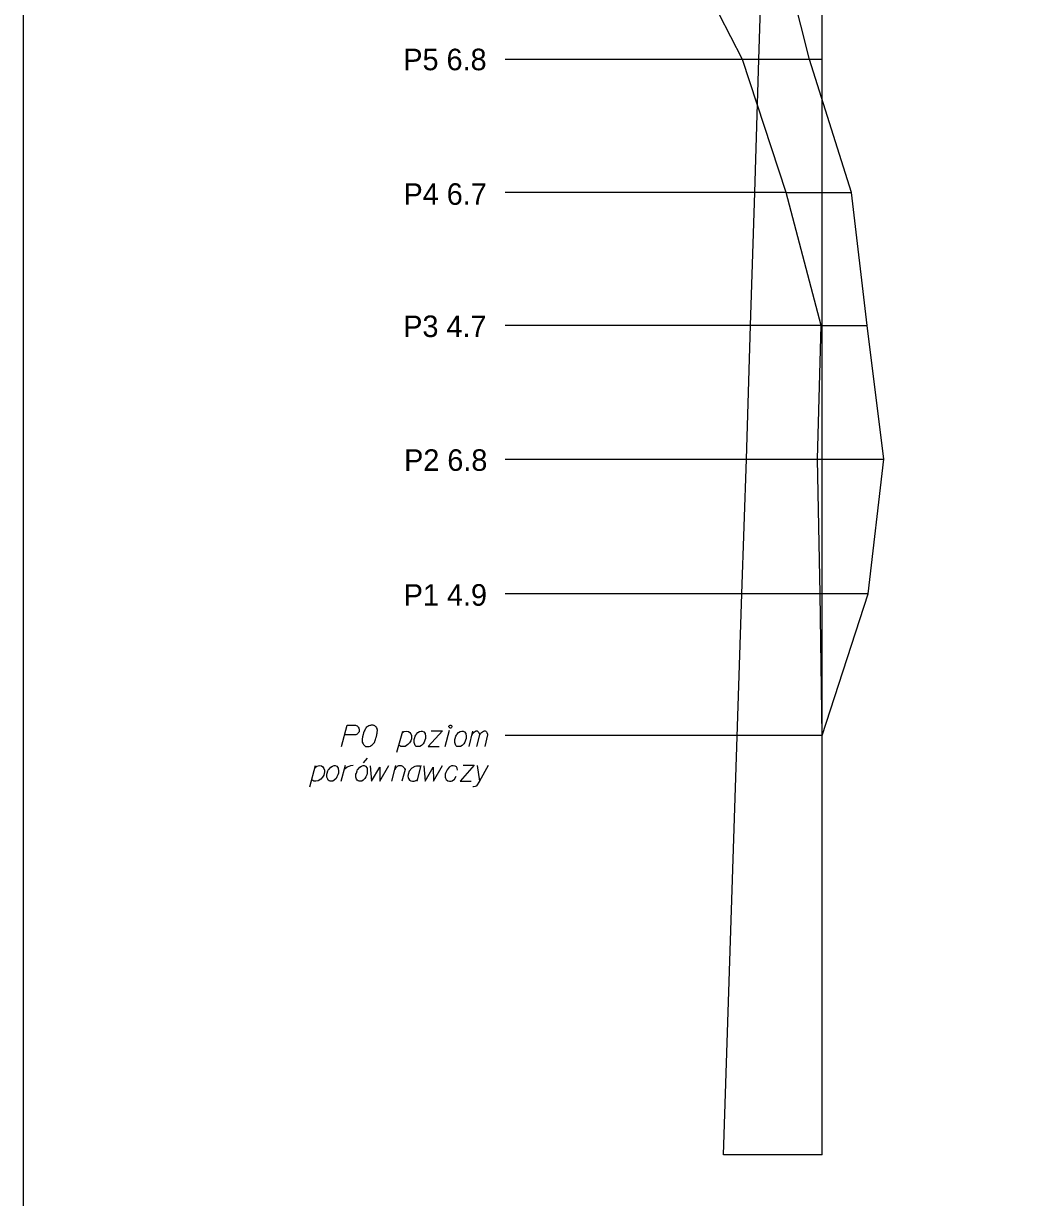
# Model space of a CAD drawing. Extents: x 138 to 264, y -75 to 121.
# Drawn here: x 227.52 to 237.85, y -57.33 to -45.34 of the extents above; entities that cross this region are included whole.
import ezdxf

# ---------------------------------------------------------------- set-up
doc = ezdxf.new("R2010")
doc.units = 0
for name, color, linetype in [('15 listopad 2008', 7, 'Continuous'), ('Ramka do drukowania', 7, 'Continuous'), ('Standart wykresów', 7, 'Continuous'), ('Wykresy 4 maj 2008', 7, 'Continuous')]:
    doc.layers.add(name, color=color, linetype=linetype)

msp = doc.modelspace()

# ---------------------------------------------------------------- linework, layer by layer
at = {"layer": '15 listopad 2008'}
msp.add_lwpolyline([(235.685, -52.61), (236.155, -51.164), (236.315, -49.788), (236.145, -48.421), (235.985, -47.063), (235.555, -45.704), (235.205, -44.313), (234.025, -42.911), (233.715, -41.918), (233.685, -40.937), (233.845, -40.478), (234.355, -39.961), (234.525, -39.493), (235.345, -38.925), (236.535, -38.4), (236.595, -38.212), (240.695, -37.514), (243.055, -37.151), (244.125, -36.895)], dxfattribs=at)
at = {"layer": 'Ramka do drukowania'}
msp.add_line((227.525, -63.621), (227.525, -33.921), dxfattribs=at)
at = {"layer": 'Standart wykresów'}
for p, q in [((235.685, -56.895), (235.685, -36.811)), ((235.038, -45.704), (235.083, -44.313)), ((234.872, -45.704), (232.448, -45.704)), ((234.996, -47.063), (235.038, -45.704)), ((235.319, -47.063), (232.448, -47.063)), ((234.953, -48.421), (234.996, -47.063)), ((235.677, -48.421), (232.448, -48.421)), ((234.911, -49.788), (234.953, -48.421)), ((235.677, -48.421), (236.145, -48.421)), ((232.448, -49.788), (235.639, -49.788)), ((234.866, -51.164), (234.911, -49.788)), ((235.666, -51.164), (232.448, -51.164)), ((234.679, -56.895), (234.866, -51.164)), ((235.685, -52.61), (232.448, -52.61)), ((235.685, -56.895), (234.679, -56.895))]:
    msp.add_line(p, q, dxfattribs=at)
for points in [[(230.774, -52.725), (230.833, -52.505), (230.908, -52.505), (230.918, -52.507), (230.923, -52.509), (230.934, -52.514), (230.94, -52.519), (230.946, -52.526), (230.951, -52.535), (230.954, -52.547), (230.956, -52.557), (230.954, -52.566), (230.953, -52.573), (230.949, -52.58), (230.946, -52.585), (230.94, -52.592), (230.934, -52.597), (230.928, -52.6), (230.92, -52.604), (230.911, -52.606), (230.807, -52.606)], [(231.089, -52.505), (231.086, -52.505), (231.076, -52.507), (231.069, -52.509), (231.063, -52.51), (231.055, -52.514), (231.044, -52.519), (231.036, -52.524), (231.027, -52.531), (231.022, -52.538), (231.017, -52.547), (231.012, -52.555), (231.006, -52.566), (231.003, -52.573), (230.999, -52.583), (230.994, -52.6), (230.989, -52.626), (230.986, -52.647), (230.986, -52.666), (230.987, -52.68), (230.994, -52.696), (230.999, -52.704), (231.008, -52.715), (231.018, -52.722), (231.024, -52.723), (231.034, -52.725), (231.043, -52.725), (231.057, -52.723), (231.069, -52.72), (231.077, -52.715), (231.089, -52.706), (231.095, -52.701), (231.102, -52.694), (231.107, -52.687), (231.11, -52.682), (231.114, -52.673), (231.115, -52.67), (231.119, -52.661), (231.122, -52.651), (231.126, -52.64), (231.128, -52.633), (231.129, -52.628), (231.131, -52.621), (231.135, -52.606), (231.136, -52.597), (231.138, -52.588), (231.14, -52.576), (231.141, -52.56), (231.141, -52.555), (231.14, -52.548), (231.138, -52.541), (231.133, -52.531), (231.128, -52.524), (231.122, -52.519), (231.115, -52.514), (231.109, -52.51), (231.103, -52.509), (231.098, -52.507), (231.089, -52.505)], [(231.883, -52.505), (231.891, -52.505), (231.897, -52.509), (231.902, -52.515), (231.902, -52.524), (231.897, -52.531), (231.891, -52.535), (231.883, -52.535), (231.878, -52.531), (231.872, -52.524), (231.872, -52.515), (231.878, -52.509), (231.883, -52.505)], [(231.341, -52.782), (231.4, -52.566)], [(231.394, -52.585), (231.412, -52.571), (231.438, -52.566), (231.458, -52.569), (231.472, -52.58), (231.483, -52.593), (231.49, -52.612), (231.491, -52.63), (231.488, -52.645), (231.483, -52.664), (231.469, -52.685), (231.451, -52.704), (231.425, -52.722), (231.403, -52.725), (231.382, -52.723), (231.36, -52.711)], [(231.588, -52.566), (231.6, -52.566), (231.614, -52.573), (231.628, -52.592), (231.63, -52.6), (231.632, -52.609), (231.632, -52.616), (231.632, -52.642), (231.626, -52.659), (231.618, -52.68), (231.607, -52.697), (231.59, -52.713), (231.574, -52.725), (231.548, -52.725), (231.538, -52.722), (231.528, -52.713), (231.522, -52.704), (231.516, -52.683), (231.516, -52.652), (231.519, -52.642), (231.526, -52.619), (231.533, -52.607), (231.536, -52.6), (231.554, -52.581), (231.571, -52.571), (231.588, -52.566)], [(231.692, -52.562), (231.805, -52.562), (231.661, -52.725), (231.772, -52.725)], [(231.834, -52.725), (231.879, -52.557)], [(232.004, -52.566), (232.016, -52.566), (232.03, -52.573), (232.044, -52.592), (232.046, -52.6), (232.047, -52.609), (232.047, -52.616), (232.047, -52.642), (232.042, -52.659), (232.033, -52.68), (232.023, -52.697), (232.006, -52.713), (231.99, -52.725), (231.964, -52.725), (231.954, -52.722), (231.943, -52.713), (231.938, -52.704), (231.931, -52.683), (231.931, -52.652), (231.935, -52.642), (231.942, -52.619), (231.949, -52.607), (231.952, -52.6), (231.969, -52.581), (231.987, -52.571), (232.004, -52.566)], [(232.077, -52.725), (232.117, -52.567)], [(232.106, -52.609), (232.115, -52.59), (232.124, -52.58), (232.134, -52.573), (232.144, -52.567), (232.151, -52.564), (232.162, -52.564), (232.165, -52.566), (232.172, -52.573), (232.179, -52.581), (232.184, -52.597), (232.186, -52.606), (232.195, -52.59), (232.205, -52.58), (232.215, -52.573), (232.226, -52.567), (232.234, -52.564), (232.243, -52.564), (232.25, -52.566), (232.255, -52.573), (232.26, -52.581), (232.266, -52.597), (232.267, -52.606), (232.238, -52.725)], [(232.156, -52.725), (232.186, -52.606)], [(231.038, -52.843), (230.995, -52.891)], [(230.451, -53.135), (230.51, -52.919)], [(230.505, -52.938), (230.522, -52.924), (230.548, -52.919), (230.569, -52.922), (230.583, -52.933), (230.593, -52.947), (230.6, -52.966), (230.602, -52.983), (230.598, -52.999), (230.593, -53.018), (230.579, -53.038), (230.562, -53.057), (230.536, -53.075), (230.513, -53.078), (230.493, -53.077), (230.47, -53.064)], [(230.699, -52.919), (230.711, -52.919), (230.725, -52.926), (230.739, -52.945), (230.74, -52.954), (230.742, -52.962), (230.742, -52.969), (230.742, -52.995), (230.737, -53.012), (230.728, -53.033), (230.718, -53.051), (230.7, -53.066), (230.685, -53.078), (230.659, -53.078), (230.648, -53.075), (230.638, -53.066), (230.633, -53.057), (230.626, -53.037), (230.626, -53.006), (230.629, -52.995), (230.636, -52.973), (230.643, -52.96), (230.647, -52.954), (230.664, -52.934), (230.681, -52.924), (230.699, -52.919)], [(230.771, -53.078), (230.815, -52.914)], [(230.804, -52.954), (230.813, -52.947), (230.832, -52.933), (230.853, -52.924), (230.868, -52.919), (230.893, -52.914)], [(230.995, -52.919), (231.007, -52.919), (231.021, -52.926), (231.035, -52.945), (231.036, -52.954), (231.038, -52.962), (231.038, -52.969), (231.038, -52.995), (231.033, -53.012), (231.024, -53.033), (231.014, -53.051), (230.997, -53.066), (230.981, -53.078), (230.955, -53.078), (230.945, -53.075), (230.934, -53.066), (230.929, -53.057), (230.922, -53.037), (230.922, -53.006), (230.926, -52.995), (230.933, -52.973), (230.939, -52.96), (230.943, -52.954), (230.96, -52.934), (230.978, -52.924), (230.995, -52.919)], [(231.068, -52.921), (231.081, -53.078), (231.165, -52.934), (231.166, -53.078), (231.258, -52.917)], [(231.288, -53.078), (231.331, -52.919)], [(231.321, -52.957), (231.326, -52.948), (231.333, -52.938), (231.338, -52.933), (231.345, -52.926), (231.352, -52.922), (231.36, -52.919), (231.369, -52.917), (231.376, -52.917), (231.385, -52.919), (231.392, -52.922), (231.398, -52.926), (231.405, -52.931), (231.412, -52.938), (231.416, -52.943), (231.419, -52.95), (231.423, -52.959), (231.392, -53.078)], [(231.582, -52.933), (231.57, -52.924), (231.541, -52.924), (231.523, -52.928), (231.492, -52.945), (231.466, -52.976), (231.454, -53.009), (231.452, -53.026), (231.454, -53.04), (231.459, -53.052), (231.47, -53.066), (231.482, -53.075), (231.501, -53.078), (231.515, -53.077), (231.528, -53.075), (231.547, -53.064)], [(231.586, -52.919), (231.544, -53.078)], [(231.615, -52.921), (231.629, -53.078), (231.712, -52.934), (231.714, -53.078), (231.806, -52.917)], [(231.958, -52.966), (231.956, -52.945), (231.948, -52.931), (231.937, -52.924), (231.916, -52.921), (231.897, -52.921), (231.873, -52.936), (231.854, -52.962), (231.84, -52.988), (231.835, -53.007), (231.835, -53.037), (231.837, -53.047), (231.844, -53.061), (231.859, -53.075), (231.877, -53.078), (231.896, -53.077), (231.906, -53.073), (231.929, -53.057), (231.946, -53.028)], [(232.019, -52.915), (232.131, -52.915), (231.987, -53.078), (232.098, -53.078)], [(232.272, -52.917), (232.183, -53.078), (232.155, -53.125), (232.149, -53.129), (232.14, -53.132), (232.123, -53.135), (232.116, -53.135)], [(232.161, -52.919), (232.183, -53.078)]]:
    msp.add_lwpolyline(points, dxfattribs=at)
at = {"layer": 'Wykresy 4 maj 2008'}
for p, q in [((235.685, -45.704), (234.872, -45.704)), ((235.319, -47.063), (235.985, -47.063)), ((235.639, -49.788), (236.315, -49.788)), ((236.155, -51.164), (235.666, -51.164))]:
    msp.add_line(p, q, dxfattribs=at)
msp.add_lwpolyline([(235.685, -52.61), (235.666, -51.164), (235.639, -49.788), (235.677, -48.421), (235.319, -47.063), (234.872, -45.704), (234.156, -44.313), (233.07, -42.911), (233.567, -41.918), (233.344, -40.937), (233.777, -40.478), (234.265, -39.961), (234.83, -39.493), (235.733, -38.925), (237.534, -38.4), (237.155, -38.212), (241.683, -37.514), (244.665, -37.151), (246.042, -36.895)], dxfattribs=at)

# ---------------------------------------------------------------- texts
for s, p in [('P5 6.8', (231.406, -45.814)), ('P4 6.7', (231.408, -47.189)), ('P3 4.7', (231.405, -48.54)), ('P2 6.8', (231.414, -49.907)), ('P1 4.9', (231.41, -51.285))]:
    msp.add_text(s, height=0.22, dxfattribs=at).set_placement(p)

doc.saveas('drawing.dxf')
